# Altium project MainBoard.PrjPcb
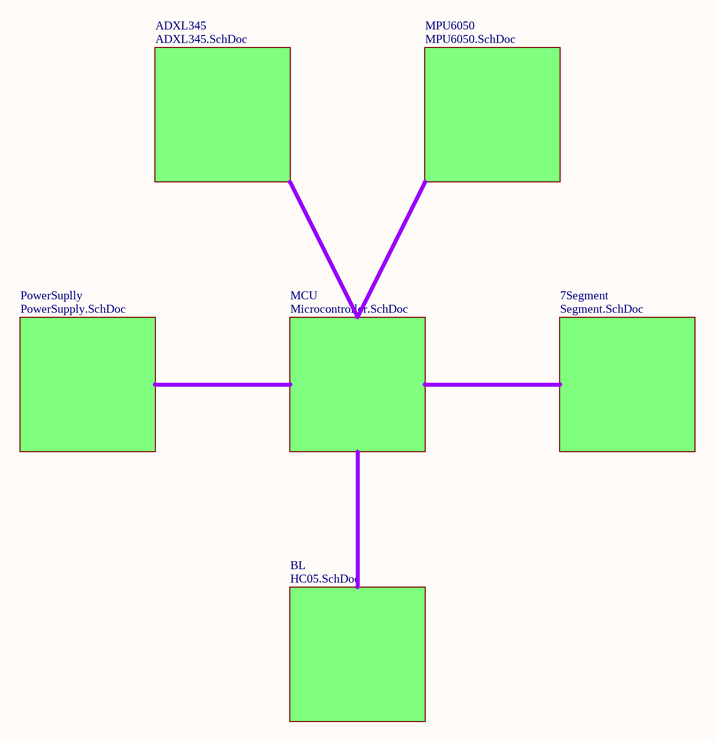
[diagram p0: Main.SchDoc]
6 sheets, 59 parts. Net scope: global (net labels, ports and power ports of the same name join across sheets).
Board file: PCB1.PcbDoc
Sheets:
  Main.SchDoc
    MCU = Microcontroller.SchDoc
    PowerSuplly = PowerSupply.SchDoc
    ADXL345 = ADXL345.SchDoc
    7Segment = Segment.SchDoc
    BL = HC05.SchDoc

## Sheet Main.SchDoc
size A; SheetNumber: 1; SheetTotal: 7

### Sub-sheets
7Segment = Segment.SchDoc: no entries
ADXL345 = ADXL345.SchDoc: no entries
BL = HC05.SchDoc: no entries
MCU = Microcontroller.SchDoc: no entries
MPU6050 = MPU6050.SchDoc (file not in this document): no entries
PowerSuplly = PowerSupply.SchDoc: no entries

## Sheet Microcontroller.SchDoc
size A; SheetNumber: 2; SheetTotal: 6
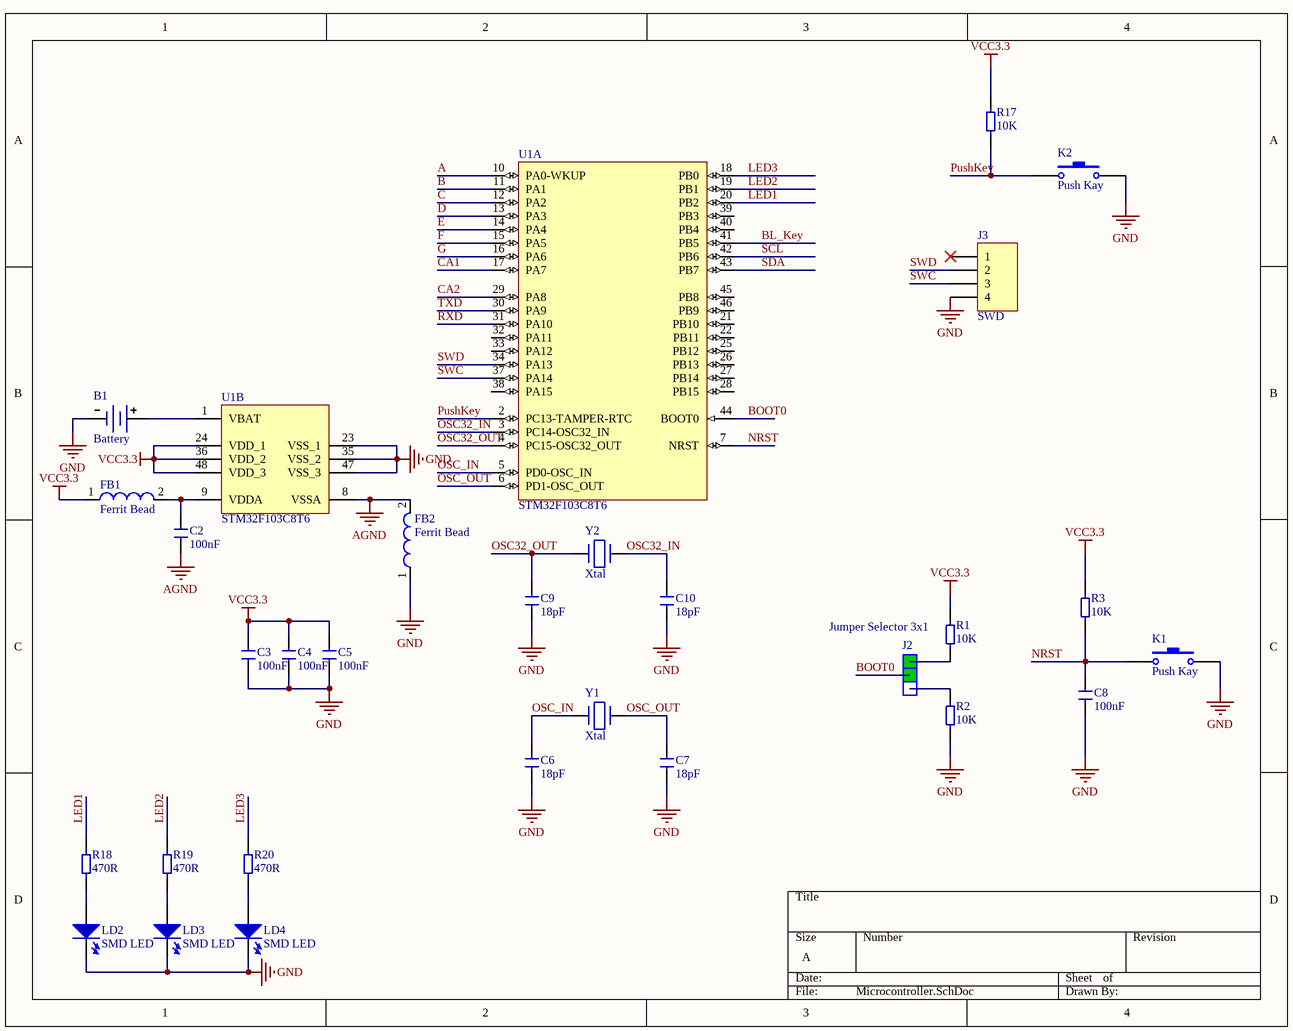
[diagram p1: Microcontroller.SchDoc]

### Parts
B1  Battery  [Battery socket SMD]
C2  Capacitor SMD  [1206 Capacitor]  (value not drawn)
C3  Capacitor SMD  [1206 Capacitor]  (value not drawn)
C4  Capacitor SMD  [1206 Capacitor]  (value not drawn)
C5  Capacitor SMD  [1206 Capacitor]  (value not drawn)
C6  Capacitor SMD  [1206 Capacitor]  (value not drawn)
C7  Capacitor SMD  [1206 Capacitor]  (value not drawn)
C8  Capacitor SMD  [1206 Capacitor]  (value not drawn)
C9  Capacitor SMD  [1206 Capacitor]  (value not drawn)
C10  Capacitor SMD  [1206 Capacitor]  (value not drawn)
FB1  Ferrit Bead  [1206 Ferrit Bead]
FB2  Ferrit Bead  [1206 Ferrit Bead]
J2  Jumper Selector 3x1  [Jumper Selector 3x1 SMT]
J3  SWD  [CON WF_4]
K1  Push Kay  [Push Kay 4 KFC]
K2  Push Kay  [Push Kay 4 KFC]
LD2  SMD LED  [LED_1206 RED]
LD3  SMD LED  [LED_1206 RED]
LD4  SMD LED  [LED_1206 RED]
R1  Resistor SMD  [1206 Resistor]  (value not drawn)
R2  Resistor SMD  [1206 Resistor]  (value not drawn)
R3  Resistor SMD  [1206 Resistor]  (value not drawn)
R17  Resistor SMD  [1206 Resistor]  (value not drawn)
R18  Resistor SMD  [1206 Resistor]  (value not drawn)
R19  Resistor SMD  [1206 Resistor]  (value not drawn)
R20  Resistor SMD  [1206 Resistor]  (value not drawn)
U1  STM32F103C8T6  [STM-LQFP48_N]  (parts A,B of 2)
Y1  Xtal  [Crystal SMD]
Y2  Xtal  [Xtal 32.782khz]

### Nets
AGND: C2.1 FB2.2 U1.8(VSSA)
GND: B1.2(-) C3.1 C4.1 C5.1 C6.1 C7.1 C8.1 C9.1 C10.1 FB2.1 J3.4 K1.2 K2.2 LD2.2(K) LD3.2(K) LD4.2(K) R2.1 U1.23(VSS_1) U1.35(VSS_2) U1.47(VSS_3)
VCC3.3: C3.2 C4.2 C5.2 FB1.1 R1.2 R3.2 R17.2 U1.24(VDD_1) U1.36(VDD_2) U1.48(VDD_3)
A: U1.10(PA0-WKUP)
B: U1.11(PA1)
BL_Key: U1.41(PB5)
BOOT0: J2.2 U1.44(BOOT0)
C: U1.12(PA2)
CA1: U1.17(PA7)
CA2: U1.29(PA8)
D: U1.13(PA3)
E: U1.14(PA4)
F: U1.15(PA5)
G: U1.16(PA6)
LED1: R18.2 U1.20(PB2)
LED2: R19.2 U1.19(PB1)
LED3: R20.2 U1.18(PB0)
NRST: C8.2 K1.1 R3.1 U1.7(NRST)
OSC32_IN: C10.2 U1.3(PC14-OSC32_IN) Y2.1
OSC32_OUT: C9.2 U1.4(PC15-OSC32_OUT) Y2.2
OSC_IN: C6.2 U1.5(PD0-OSC_IN) Y1.2
OSC_OUT: C7.2 U1.6(PD1-OSC_OUT) Y1.1
PushKey: K2.1 R17.1 U1.2(PC13-TAMPER-RTC)
RXD: U1.31(PA10)
SCL: U1.42(PB6)
SDA: U1.43(PB7)
SWC: J3.3 U1.37(PA14)
SWD: J3.2 U1.34(PA13)
TXD: U1.30(PA9)
NetB1_1: B1.1(+) U1.1(VBAT)
NetC2_2: C2.2 FB1.2 U1.9(VDDA)
NetJ2_1: J2.1 R1.1
NetJ2_3: J2.3 R2.2
NetLD2_1: LD2.1(A) R18.1
NetLD3_1: LD3.1(A) R19.1
NetLD4_1: LD4.1(A) R20.1

Not connected (* = marked no-connect by the designer): J3 1*; U1 21(PB10) 22(PB11) 25(PB12) 26(PB13) 27(PB14) 28(PB15) 32(PA11) 33(PA12) 38(PA15) 39(PB3) 40(PB4) 45(PB8) 46(PB9)

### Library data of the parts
B1 = Battry Backup
J3 = Header 4 PIN Telecom.: Header, 4-Pin Telecom.; Designer: Abbas Basereh
LD2-LD4 = LED SMD
U1 = STM32F103C8T6: ARM Cortex-M3 32-bit MCU, 64 KB Flash, 20 KB Internal RAM, 37 I/Os, 48-pin LQFP, -40 to 85 degC, Tray; A/D Converter: 2x12-bit (10 Channel); FLASH Size (Prog) (kB): 64; I/Os (High Current): 37; Internal RAM Size (kB): 20; Operating Frequency(F) (Processor speed) (MHz): 72; Supply Voltage(Vcc) min (V): 2

## Sheet PowerSupply.SchDoc
size A; SheetNumber: 3; SheetTotal: 3
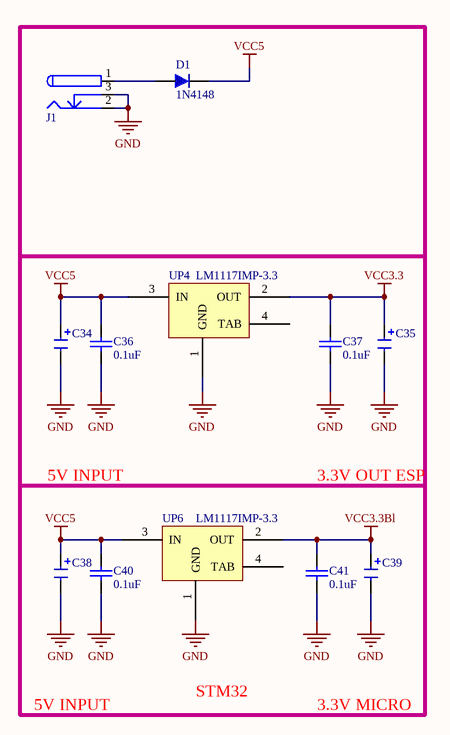
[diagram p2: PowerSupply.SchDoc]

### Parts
C34  (no value)  [CAPACITOR RADIAL SMT size F]
C35  (no value)  [CAPACITOR RADIAL SMT size F]
C36  0.1uF  [CAPC4817X12N]
C37  0.1uF  [CAPC4817X12N]
C38  (no value)  [CAPACITOR RADIAL SMT size F]
C39  (no value)  [CAPACITOR RADIAL SMT size F]
C40  0.1uF  [CAPC4817X12N]
C41  0.1uF  [CAPC4817X12N]
D1  1N4148  [Diode 1n4148 SMD]
J1  DC Power Jack  [DC Power Jack 1]  (value not drawn)
UP4  LM1117IMP-3.3  [SOT223_4]
UP6  LM1117IMP-3.3  [SOT223_4]

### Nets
GND: C34.2 C35.2 C36.1 C37.1 C38.2 C39.2 C40.1 C41.1 J1.2 J1.3 UP4.1(GND) UP6.1(GND)
VCC3.3: C35.1 C37.2 UP4.2(OUT)
VCC3.3Bl: C39.1 C41.2 UP6.2(OUT)
VCC5: C34.1 C36.2 C38.1 C40.2 D1.2 UP4.3(IN) UP6.3(IN)
NetD1_1: D1.1 J1.1

Not connected (* = marked no-connect by the designer): UP4 4(TAB); UP6 4(TAB)

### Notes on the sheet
- 5V INPUT
- 3.3V OUT ESP
- STM32
- 3.3V MICRO

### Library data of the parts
C34 C35 C38 C39 = Capacitor Tantalium
C36 C37 C40 C41 = CAP SMD 1206: CAP 1206; Designer: Abbas Basereh
D1 = 1N4148 SMD: General Semicoductor
J1 = DC Power Jack: DC Power Jack. Center Pin 2.5mm. Diameter: 5.7mm; Designer: Ali Hafizi; Company: Personal; Project Name: Laser
UP4 UP6 = LM1117IMP-x.x: x.x Volt, 800mA Low-Dropout Linear Regulator, 4-pin SOT-223; Designer: Abbas Basereh

## Sheet ADXL345.SchDoc
size A; SheetNumber: 6; SheetTotal: 6
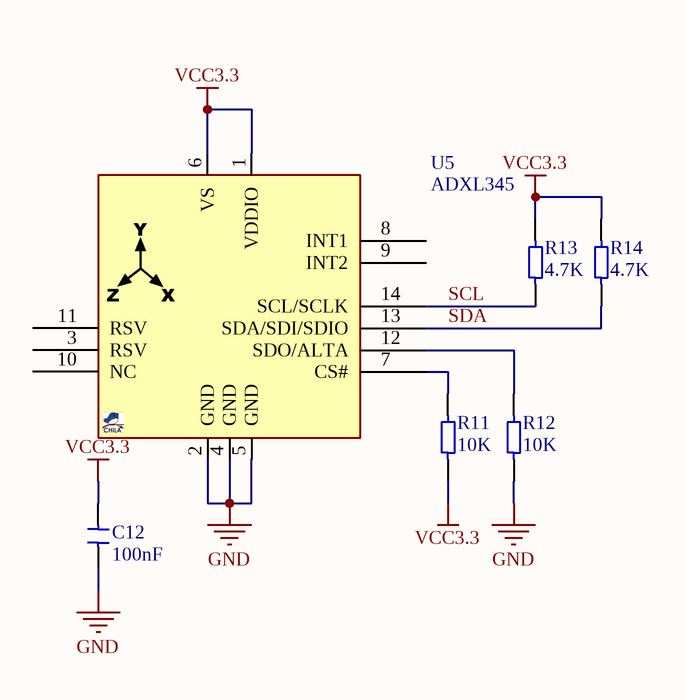
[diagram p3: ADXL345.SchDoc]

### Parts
C12  Capacitor SMD  [1206 Capacitor]  (value not drawn)
R11  Resistor SMD  [1206 Resistor]  (value not drawn)
R12  Resistor SMD  [1206 Resistor]  (value not drawn)
R13  Resistor SMD  [1206 Resistor]  (value not drawn)
R14  Resistor SMD  [1206 Resistor]  (value not drawn)
U5  ADXL345  [QFN80_14_5X3]

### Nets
GND: C12.1 R12.1 U5.2(GND) U5.4(GND) U5.5(GND)
VCC3.3: C12.2 R11.1 R13.2 R14.2 U5.1(VDDIO) U5.6(VS)
SCL: R13.1 U5.14(SCL/SCLK)
SDA: R14.1 U5.13(SDA/SDI/SDIO)
NetR11_2: R11.2 U5.7(CS#)
NetR12_2: R12.2 U5.12(SDO/ALTA)

Not connected (* = marked no-connect by the designer): U5 3(RSV) 8(INT1) 9(INT2) 10(NC) 11(RSV)

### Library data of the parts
U5 = ADXL345_LGA14: Sensor, Accelerometer Digital, 3-Axis; MANF: Analog Devices

## Sheet Segment.SchDoc
size A; SheetNumber: 5; SheetTotal: 6
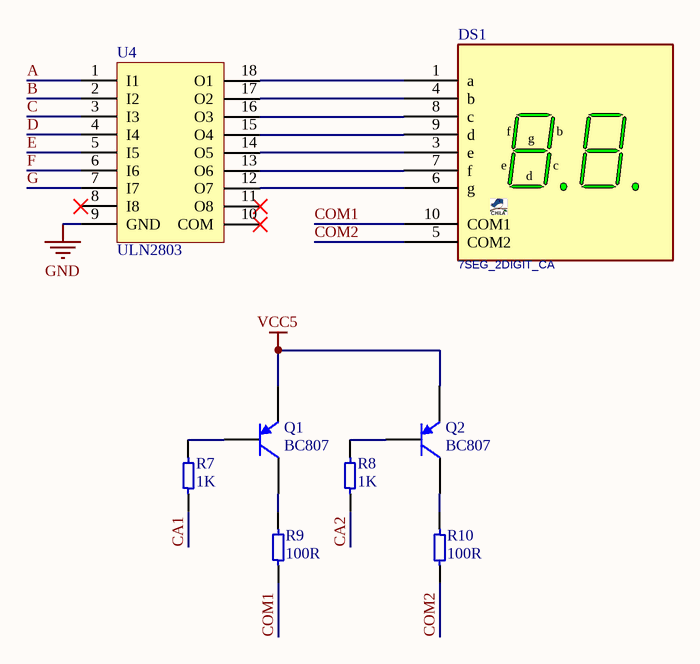
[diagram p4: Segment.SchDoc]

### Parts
DS1  7SEG_2DIGIT_CA  [7SEGX2_10_03INCH]
Q1  BC807  [SOT-23]
Q2  BC807  [SOT-23]
R7  Resistor SMD  [1206 Resistor]  (value not drawn)
R8  Resistor SMD  [1206 Resistor]  (value not drawn)
R9  Resistor SMD  [1206 Resistor]  (value not drawn)
R10  Resistor SMD  [1206 Resistor]  (value not drawn)
U4  ULN2803  [SOIC18]

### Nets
GND: U4.9(GND)
VCC5: Q1.1(E) Q2.1(E)
A: U4.1(I1)
B: U4.2(I2)
C: U4.3(I3)
CA1: R7.1
CA2: R8.1
COM1: DS1.10(COM1) R9.1
COM2: DS1.5(COM2) R10.2
D: U4.4(I4)
E: U4.5(I5)
F: U4.6(I6)
G: U4.7(I7)
NetDS1_1: DS1.1(a) U4.18(O1)
NetDS1_3: DS1.3(e) U4.14(O5)
NetDS1_4: DS1.4(b) U4.17(O2)
NetDS1_6: DS1.6(g) U4.12(O7)
NetDS1_7: DS1.7(f) U4.13(O6)
NetDS1_8: DS1.8(c) U4.16(O3)
NetDS1_9: DS1.9(d) U4.15(O4)
NetQ1_2: Q1.2(C) R9.2
NetQ1_3: Q1.3(B) R7.2
NetQ2_2: Q2.2(C) R10.1
NetQ2_3: Q2.3(B) R8.2

Not connected (* = marked no-connect by the designer): U4 8(I8)* 10(COM)* 11(O8)*

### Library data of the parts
DS1 = 7SEG_2DIGIT_CA_GRN_0.3INCH_10: 7SEGMENT, 2DIGIT, common cathode; MANF: Kingbright; MANF_P#: DA03-11GWA; PARAM: 10~20mA, 2~2.2V, -40~85oC

## Sheet HC05.SchDoc
size A; SheetNumber: 4; SheetTotal: 7
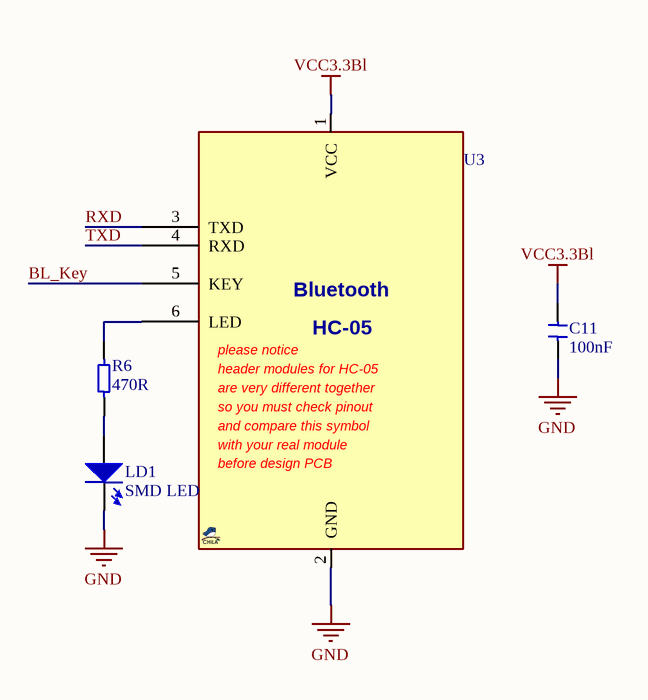
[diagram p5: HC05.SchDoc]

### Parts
C11  Capacitor SMD  [1206 Capacitor]  (value not drawn)
LD1  SMD LED  [LED_1206 RED]
R6  Resistor SMD  [1206 Resistor]  (value not drawn)
U3  HC-05  [BT_HC06]  (value not drawn)

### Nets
GND: C11.1 LD1.2(K) U3.2(GND)
VCC3.3Bl: C11.2 U3.1(VCC)
BL_Key: U3.5(KEY)
RXD: U3.3(TXD)
TXD: U3.4(RXD)
NetLD1_1: LD1.1(A) R6.1
NetR6_2: R6.2 U3.6(LED)

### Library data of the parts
LD1 = LED SMD
U3 = BT_HC-05_HDR: Bluetooth Module, 2Mbps, 8Mb flash, 3.1~4.2V

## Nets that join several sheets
GND: Microcontroller (20 pins), PowerSupply (12 pins), ADXL345 (5 pins), Segment (U4.9), HC05 (C11.1 LD1.2 U3.2)
VCC3.3: Microcontroller (10 pins), PowerSupply (C35.1 C37.2 UP4.2), ADXL345 (6 pins)
VCC3.3Bl: PowerSupply (C39.1 C41.2 UP6.2), HC05 (C11.2 U3.1)
VCC5: PowerSupply (7 pins), Segment (Q1.1 Q2.1)
A: Microcontroller (U1.10), Segment (U4.1)
B: Microcontroller (U1.11), Segment (U4.2)
BL_Key: Microcontroller (U1.41), HC05 (U3.5)
C: Microcontroller (U1.12), Segment (U4.3)
CA1: Microcontroller (U1.17), Segment (R7.1)
CA2: Microcontroller (U1.29), Segment (R8.1)
D: Microcontroller (U1.13), Segment (U4.4)
E: Microcontroller (U1.14), Segment (U4.5)
F: Microcontroller (U1.15), Segment (U4.6)
G: Microcontroller (U1.16), Segment (U4.7)
RXD: Microcontroller (U1.31), HC05 (U3.3)
SCL: Microcontroller (U1.42), ADXL345 (R13.1 U5.14)
SDA: Microcontroller (U1.43), ADXL345 (R14.1 U5.13)
TXD: Microcontroller (U1.30), HC05 (U3.4)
